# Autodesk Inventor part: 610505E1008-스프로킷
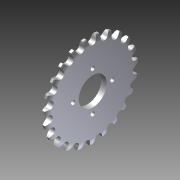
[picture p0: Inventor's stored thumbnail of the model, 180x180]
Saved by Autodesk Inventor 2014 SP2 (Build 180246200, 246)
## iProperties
Created: 2021-05
Part Number: 610505E1008-스프로킷
Material: Generic
Document SubType Name: Modeling
Designer: 거성
Density: 1 g/cm^3
Appearance: Default
Author: 거성
Title: C:\Users\거성\Desktop\610505E1008\610505E1008-스프로킷.stp
Creation Date: 2021-05-15
Sending System: Autodesk Inventor 2014
Preprocessor: ST-DEVELOPER v15.2
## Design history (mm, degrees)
node "610505E1008-스프로킷1"
node "솔리드1"
node "기준1"
